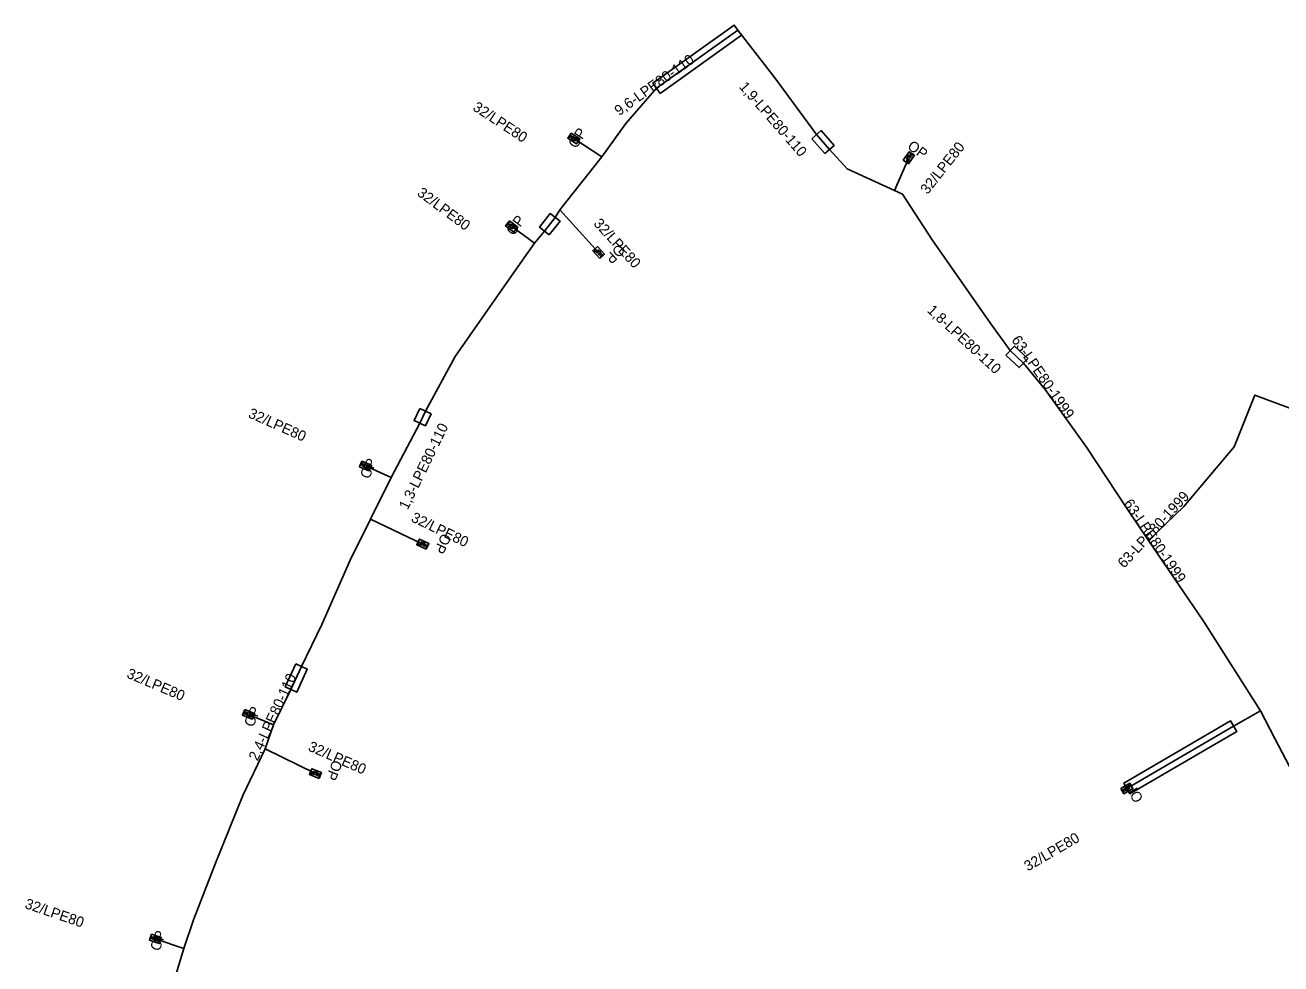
# Model space of a CAD drawing. Extents: x -762509 to -761250, y -1153000 to -1152256.
# Drawn here: x -761781.8 to -761661, y -1152346.7 to -1152256.4 of the extents above; entities that cross this region are included whole.
import ezdxf

# ---------------------------------------------------------------- set-up
doc = ezdxf.new("R2010")
doc.units = 0
for name, color, linetype in [('Vrstva 21', 7, 'Continuous'), ('Vrstva 29', 7, 'Continuous'), ('Vrstva 31', 7, 'Continuous'), ('Vrstva 32', 7, 'Continuous')]:
    doc.layers.add(name, color=color, linetype=linetype)

msp = doc.modelspace()

# ---------------------------------------------------------------- linework, layer by layer
at = {"layer": 'Vrstva 21'}
for points in [[(-761673.77, -1152305.98), (-761675.83, -1152302.94), (-761679.74, -1152297), (-761683.71, -1152291.44), (-761685.79, -1152288.91), (-761687.08, -1152287.72), (-761688.93, -1152285.15), (-761694.57, -1152277.07), (-761697.42, -1152272.67), (-761698.2, -1152272.31), (-761702.76, -1152270.23), (-761704.45, -1152268.37), (-761705.69, -1152266.95), (-761709.69, -1152261.5), (-761713.25, -1152256.91), (-761721.08, -1152262.49), (-761724.02, -1152265.89), (-761726.33, -1152269.1), (-761730.39, -1152274.19), (-761730.83, -1152274.91), (-761731.86, -1152276.22), (-761732.83, -1152277.4), (-761735.02, -1152280.54), (-761740.43, -1152288.27), (-761743.3, -1152293.55), (-761743.85, -1152294.7), (-761746.6, -1152299.91), (-761748.59, -1152303.91), (-761750.53, -1152307.87), (-761753.27, -1152314.05), (-761755.21, -1152318.09), (-761756.23, -1152320.31), (-761757.91, -1152323.71), (-761758.7, -1152326.02), (-761760.86, -1152330.5), (-761763.48, -1152337), (-761765.62, -1152342.44), (-761766.55, -1152345.22), (-761767.81, -1152349.42)], [(-761673.77, -1152305.98), (-761670.38, -1152302.71), (-761665.53, -1152296.98), (-761663.56, -1152291.99), (-761658.21, -1152293.99), (-761650.05, -1152297.02), (-761649.29, -1152297.62), (-761646.99, -1152299.04), (-761639.92, -1152302.07), (-761633.99, -1152304.61), (-761631.07, -1152304.65), (-761627.14, -1152305.92), (-761615.71, -1152310.97), (-761613.66, -1152306.5), (-761596.11, -1152314.22), (-761587.24, -1152318.01), (-761582.89, -1152319.81)], [(-761655.26, -1152337.2), (-761661.63, -1152325.02), (-761663.01, -1152322.34), (-761668.47, -1152313.73), (-761673.77, -1152305.98)]]:
    msp.add_lwpolyline(points, dxfattribs=at)
at = {"layer": 'Vrstva 29'}
for points in [[(-761720.73, -1152262.98), (-761712.9, -1152257.4), (-761713.6, -1152256.42), (-761721.43, -1152262)], [(-761706.14, -1152267.34), (-761704.9, -1152268.76), (-761704, -1152267.98), (-761705.24, -1152266.56)], [(-761731.39, -1152276.59), (-761730.36, -1152275.28), (-761731.3, -1152274.54), (-761732.33, -1152275.85)], [(-761687.49, -1152288.16), (-761686.2, -1152289.35), (-761685.38, -1152288.47), (-761686.67, -1152287.28)], [(-761743.84, -1152293.29), (-761744.39, -1152294.44), (-761743.31, -1152294.96), (-761742.76, -1152293.81)], [(-761755.76, -1152317.84), (-761756.78, -1152320.06), (-761755.68, -1152320.56), (-761754.66, -1152318.34)], [(-761675.56, -1152330.34), (-761665.29, -1152324.35), (-761665.89, -1152323.31), (-761676.16, -1152329.3)]]:
    msp.add_lwpolyline(points, close=True, dxfattribs=at)
at = {"layer": 'Vrstva 31'}
for points in [[(-761726.33, -1152269.1), (-761729.04, -1152267.32)], [(-761698.2, -1152272.31), (-761696.82, -1152269.17)], [(-761730.39, -1152274.19), (-761726.65, -1152278.28)], [(-761732.83, -1152277.4), (-761735.01, -1152275.78)], [(-761746.6, -1152299.91), (-761749.07, -1152298.81)], [(-761748.59, -1152303.91), (-761743.55, -1152306.33)], [(-761757.91, -1152323.71), (-761760.31, -1152322.69)], [(-761663.01, -1152322.34), (-761665.59, -1152323.83), (-761675.86, -1152329.82)], [(-761758.7, -1152326.02), (-761753.88, -1152328.38)], [(-761766.55, -1152345.22), (-761769.28, -1152344.28)]]:
    msp.add_lwpolyline(points, dxfattribs=at)
at = {"layer": 'Vrstva 32'}
for p, q in [((-761729.278, -1152266.954), (-761729.47, -1152267.246)), ((-761729.369, -1152267.092), (-761729.201, -1152267.202)), ((-761729.302, -1152267.357), (-761729.11, -1152267.064)), ((-761728.969, -1152267.576), (-761728.777, -1152267.283)), ((-761697.079, -1152269.232), (-761696.793, -1152269.434)), ((-761696.848, -1152268.906), (-761696.563, -1152269.109)), ((-761696.446, -1152268.945), (-761696.732, -1152268.742)), ((-761696.581, -1152268.849), (-761696.697, -1152269.013)), ((-761735.227, -1152275.401), (-761735.436, -1152275.682)), ((-761735.325, -1152275.533), (-761735.164, -1152275.653)), ((-761735.274, -1152275.802), (-761735.066, -1152275.521)), ((-761734.954, -1152276.04), (-761734.745, -1152275.759)), ((-761726.659, -1152278.015), (-761726.915, -1152278.254)), ((-761726.386, -1152278.306), (-761726.642, -1152278.545)), ((-761726.385, -1152278.58), (-761726.522, -1152278.433)), ((-761726.505, -1152278.692), (-761726.249, -1152278.453)), ((-761749.365, -1152298.487), (-761749.507, -1152298.807)), ((-761749.432, -1152298.638), (-761749.248, -1152298.72)), ((-761749.323, -1152298.889), (-761749.181, -1152298.569)), ((-761748.959, -1152299.051), (-761748.817, -1152298.731)), ((-761743.655, -1152306.086), (-761743.806, -1152306.402)), ((-761743.295, -1152306.258), (-761743.446, -1152306.574)), ((-761743.194, -1152306.512), (-761743.375, -1152306.425)), ((-761743.265, -1152306.661), (-761743.114, -1152306.345)), ((-761760.61, -1152322.373), (-761760.747, -1152322.695)), ((-761760.674, -1152322.525), (-761760.489, -1152322.603)), ((-761760.562, -1152322.773), (-761760.425, -1152322.451)), ((-761760.194, -1152322.929), (-761760.058, -1152322.607)), ((-761754.001, -1152328.143), (-761754.131, -1152328.467)), ((-761753.63, -1152328.291), (-761753.761, -1152328.616)), ((-761753.513, -1152328.538), (-761753.699, -1152328.463)), ((-761753.574, -1152328.691), (-761753.444, -1152328.366)), ((-761676.294, -1152329.871), (-761676.118, -1152330.173)), ((-761676.211, -1152330.013), (-761676.037, -1152329.912)), ((-761675.944, -1152330.072), (-761676.12, -1152329.77)), ((-761675.599, -1152329.871), (-761675.776, -1152329.569)), ((-761769.601, -1152343.984), (-761769.715, -1152344.315)), ((-761769.654, -1152344.14), (-761769.464, -1152344.206)), ((-761769.525, -1152344.381), (-761769.411, -1152344.05)), ((-761769.147, -1152344.51), (-761769.033, -1152344.18))]:
    msp.add_line(p, q, dxfattribs=at)
for points in [[(-761729.293, -1152266.794), (-761728.457, -1152267.343), (-761728.787, -1152267.845), (-761729.623, -1152267.296), (-761729.293, -1152266.794)], [(-761729.028, -1152267.118), (-761729.165, -1152267.328), (-761729.181, -1152267.377), (-761729.173, -1152267.422), (-761729.147, -1152267.459), (-761729.123, -1152267.475), (-761729.078, -1152267.484), (-761729.036, -1152267.472), (-761728.997, -1152267.439), (-761728.86, -1152267.229)], [(-761728.777, -1152267.283), (-761728.668, -1152267.355), (-761728.642, -1152267.392), (-761728.639, -1152267.413), (-761728.645, -1152267.449), (-761728.673, -1152267.49), (-761728.702, -1152267.51), (-761728.724, -1152267.516), (-761728.768, -1152267.507), (-761728.877, -1152267.435)], [(-761696.287, -1152268.936), (-761696.865, -1152269.751), (-761697.354, -1152269.404), (-761696.776, -1152268.589), (-761696.287, -1152268.936)], [(-761696.793, -1152269.434), (-761696.869, -1152269.54), (-761696.907, -1152269.565), (-761696.928, -1152269.568), (-761696.964, -1152269.56), (-761697.004, -1152269.531), (-761697.023, -1152269.501), (-761697.027, -1152269.479), (-761697.017, -1152269.435), (-761696.942, -1152269.329)], [(-761696.62, -1152269.19), (-761696.825, -1152269.044), (-761696.873, -1152269.028), (-761696.918, -1152269.034), (-761696.956, -1152269.058), (-761696.972, -1152269.082), (-761696.983, -1152269.126), (-761696.973, -1152269.169), (-761696.941, -1152269.208), (-761696.736, -1152269.354)], [(-761735.233, -1152275.241), (-761734.43, -1152275.837), (-761734.788, -1152276.319), (-761735.591, -1152275.722), (-761735.233, -1152275.241)], [(-761734.986, -1152275.58), (-761735.136, -1152275.781), (-761735.154, -1152275.829), (-761735.149, -1152275.874), (-761735.125, -1152275.913), (-761735.102, -1152275.93), (-761735.058, -1152275.941), (-761735.015, -1152275.932), (-761734.975, -1152275.901), (-761734.825, -1152275.7)], [(-761734.745, -1152275.759), (-761734.641, -1152275.836), (-761734.618, -1152275.875), (-761734.615, -1152275.897), (-761734.623, -1152275.932), (-761734.653, -1152275.972), (-761734.684, -1152275.99), (-761734.706, -1152275.994), (-761734.75, -1152275.982), (-761734.854, -1152275.905)], [(-761726.528, -1152278.851), (-761727.211, -1152278.12), (-761726.772, -1152277.71), (-761726.09, -1152278.441), (-761726.528, -1152278.851)], [(-761726.915, -1152278.254), (-761727.003, -1152278.159), (-761727.02, -1152278.116), (-761727.018, -1152278.094), (-761727.003, -1152278.062), (-761726.967, -1152278.027), (-761726.933, -1152278.015), (-761726.911, -1152278.015), (-761726.87, -1152278.034), (-761726.782, -1152278.129)], [(-761726.71, -1152278.473), (-761726.526, -1152278.302), (-761726.5, -1152278.258), (-761726.497, -1152278.213), (-761726.513, -1152278.17), (-761726.533, -1152278.149), (-761726.574, -1152278.13), (-761726.618, -1152278.131), (-761726.664, -1152278.155), (-761726.847, -1152278.326)], [(-761749.405, -1152298.332), (-761748.492, -1152298.739), (-761748.736, -1152299.287), (-761749.649, -1152298.88), (-761749.405, -1152298.332)], [(-761749.091, -1152298.609), (-761749.193, -1152298.839), (-761749.2, -1152298.889), (-761749.185, -1152298.932), (-761749.154, -1152298.964), (-761749.127, -1152298.976), (-761749.082, -1152298.978), (-761749.042, -1152298.959), (-761749.009, -1152298.92), (-761748.907, -1152298.691)], [(-761748.817, -1152298.731), (-761748.698, -1152298.784), (-761748.666, -1152298.817), (-761748.659, -1152298.838), (-761748.66, -1152298.873), (-761748.68, -1152298.919), (-761748.706, -1152298.943), (-761748.727, -1152298.952), (-761748.772, -1152298.95), (-761748.891, -1152298.898)], [(-761743.228, -1152306.817), (-761744.131, -1152306.385), (-761743.872, -1152305.844), (-761742.97, -1152306.275), (-761743.228, -1152306.817)], [(-761743.806, -1152306.402), (-761743.923, -1152306.346), (-761743.954, -1152306.312), (-761743.96, -1152306.292), (-761743.959, -1152306.256), (-761743.937, -1152306.211), (-761743.91, -1152306.187), (-761743.89, -1152306.179), (-761743.845, -1152306.182), (-761743.727, -1152306.238)], [(-761743.535, -1152306.531), (-761743.427, -1152306.305), (-761743.419, -1152306.255), (-761743.432, -1152306.212), (-761743.463, -1152306.178), (-761743.489, -1152306.166), (-761743.534, -1152306.163), (-761743.575, -1152306.18), (-761743.608, -1152306.218), (-761743.717, -1152306.445)], [(-761760.653, -1152322.219), (-761759.733, -1152322.61), (-761759.967, -1152323.162), (-761760.888, -1152322.771), (-761760.653, -1152322.219)], [(-761760.334, -1152322.49), (-761760.432, -1152322.721), (-761760.438, -1152322.772), (-761760.422, -1152322.814), (-761760.39, -1152322.846), (-761760.364, -1152322.858), (-761760.318, -1152322.858), (-761760.279, -1152322.839), (-761760.247, -1152322.8), (-761760.149, -1152322.569)], [(-761760.058, -1152322.607), (-761759.938, -1152322.658), (-761759.906, -1152322.69), (-761759.898, -1152322.711), (-761759.898, -1152322.747), (-761759.918, -1152322.793), (-761759.944, -1152322.818), (-761759.964, -1152322.826), (-761760.009, -1152322.826), (-761760.129, -1152322.775)], [(-761753.528, -1152328.844), (-761754.456, -1152328.471), (-761754.232, -1152327.915), (-761753.305, -1152328.288), (-761753.528, -1152328.844)], [(-761754.131, -1152328.467), (-761754.252, -1152328.419), (-761754.284, -1152328.387), (-761754.292, -1152328.367), (-761754.293, -1152328.331), (-761754.274, -1152328.285), (-761754.249, -1152328.259), (-761754.229, -1152328.25), (-761754.184, -1152328.25), (-761754.063, -1152328.298)], [(-761753.853, -1152328.579), (-761753.759, -1152328.346), (-761753.754, -1152328.296), (-761753.77, -1152328.253), (-761753.803, -1152328.222), (-761753.83, -1152328.211), (-761753.875, -1152328.211), (-761753.914, -1152328.231), (-761753.946, -1152328.271), (-761754.039, -1152328.504)], [(-761676.443, -1152329.813), (-761675.579, -1152329.309), (-761675.277, -1152329.828), (-761676.141, -1152330.332), (-761676.443, -1152329.813)], [(-761676.035, -1152329.72), (-761675.908, -1152329.937), (-761675.872, -1152329.972), (-761675.828, -1152329.985), (-761675.783, -1152329.978), (-761675.758, -1152329.964), (-761675.731, -1152329.928), (-761675.722, -1152329.885), (-761675.735, -1152329.835), (-761675.861, -1152329.618)], [(-761675.776, -1152329.569), (-761675.663, -1152329.503), (-761675.619, -1152329.497), (-761675.597, -1152329.503), (-761675.569, -1152329.524), (-761675.544, -1152329.567), (-761675.539, -1152329.603), (-761675.544, -1152329.624), (-761675.572, -1152329.66), (-761675.684, -1152329.726)], [(-761769.655, -1152343.833), (-761768.709, -1152344.159), (-761768.904, -1152344.726), (-761769.85, -1152344.401), (-761769.655, -1152343.833)], [(-761769.317, -1152344.082), (-761769.399, -1152344.319), (-761769.402, -1152344.37), (-761769.383, -1152344.411), (-761769.349, -1152344.441), (-761769.321, -1152344.451), (-761769.276, -1152344.448), (-761769.238, -1152344.426), (-761769.209, -1152344.385), (-761769.127, -1152344.147)], [(-761769.033, -1152344.18), (-761768.911, -1152344.222), (-761768.876, -1152344.252), (-761768.867, -1152344.272), (-761768.865, -1152344.307), (-761768.881, -1152344.355), (-761768.905, -1152344.381), (-761768.925, -1152344.392), (-761768.97, -1152344.394), (-761769.093, -1152344.352)]]:
    msp.add_lwpolyline(points, dxfattribs=at)

# ---------------------------------------------------------------- texts
at = {"layer": 'Vrstva 21'}
for rotation, p in [(304.79534, (-761686.99, -1152286.69)), (47.43144, (-761676.11, -1152308.7)), (304.36709, (-761676.2, -1152302.41))]:
    msp.add_text('63-LPE80-1999', height=1, rotation=rotation, dxfattribs=at).set_placement(p)
at = {"layer": 'Vrstva 29'}
for s, rotation, p in [('9,6-LPE80-110', 35.47533, (-761724.68, -1152265.18)), ('1,9-LPE80-110', 311.12874, (-761713.2, -1152262.39)), ('1,8-LPE80-110', 317.30906, (-761695.13, -1152283.94)), ('1,3-LPE80-110', 64.01977, (-761745.01, -1152303.09)), ('2,4-LPE80-110', 65.23222, (-761759.45, -1152327.23))]:
    msp.add_text(s, height=1, rotation=rotation, dxfattribs=at).set_placement(p)
at = {"layer": 'Vrstva 31'}
for rotation, p in [(326.70203, (-761738.83, -1152264.54)), (326.70203, (-761738.83, -1152264.54)), (51.69001, (-761695.02, -1152272.76)), (51.69001, (-761695.02, -1152272.76)), (323.38325, (-761744.18, -1152272.73)), (323.38325, (-761744.18, -1152272.73)), (312.44059, (-761727.2, -1152275.55)), (312.44059, (-761727.2, -1152275.55)), (335.99448, (-761760.42, -1152294.1)), (335.99448, (-761760.42, -1152294.1)), (334.3516, (-761744.76, -1152304.1)), (334.3516, (-761744.76, -1152304.1)), (336.97451, (-761772.11, -1152319.13)), (336.97451, (-761772.11, -1152319.13)), (336.34536, (-761754.66, -1152326.14)), (336.34536, (-761754.66, -1152326.14)), (30.25297, (-761685.37, -1152337.81)), (30.25297, (-761685.37, -1152337.81)), (341.00027, (-761781.9, -1152341.3)), (341.00027, (-761781.9, -1152341.3))]:
    msp.add_text('32/LPE80', height=1, rotation=rotation, dxfattribs=at).set_placement(p)
at = {"layer": 'Vrstva 32'}
for rotation, p in [(56.70203, (-761728.81, -1152268.35)), (56.70203, (-761728.81, -1152268.35)), (324.65739, (-761697.04, -1152268.25)), (324.65739, (-761697.04, -1152268.25)), (53.38325, (-761734.82, -1152276.73)), (53.38325, (-761734.82, -1152276.73)), (223.02392, (-761724.69, -1152277.41)), (223.02392, (-761724.69, -1152277.41)), (65.99448, (-761748.73, -1152300.13)), (65.99448, (-761748.73, -1152300.13)), (244.44308, (-761741.68, -1152305.2)), (244.44308, (-761741.68, -1152305.2)), (66.97451, (-761759.87, -1152323.99)), (66.97451, (-761759.87, -1152323.99)), (248.09982, (-761752.18, -1152327)), (248.09982, (-761752.18, -1152327)), (120.25297, (-761674.23, -1152330.81)), (120.25297, (-761674.23, -1152330.81)), (71.00027, (-761768.87, -1152345.52)), (71.00027, (-761768.87, -1152345.52))]:
    msp.add_text('OP', height=1, rotation=rotation, dxfattribs=at).set_placement(p)

doc.saveas('drawing.dxf')
